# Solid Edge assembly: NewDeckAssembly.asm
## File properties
Author: morva
Template: Iso Metric Assembly.asm
Last saved by: morva
Revision: 17
Application: Solid Edge
Username: morva
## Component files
aksipakkdummy.par
hex_socket_countersunk_flat_head_M8x20.par
backmudcatcher.par
motorDummy.par
chargerportCap.par
Dummy.par
CableCoverPlate.par
DC Jack Panel Mount ASSY.asm
NewDeck.par
deckCover.par
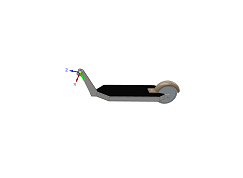
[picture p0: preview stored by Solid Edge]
